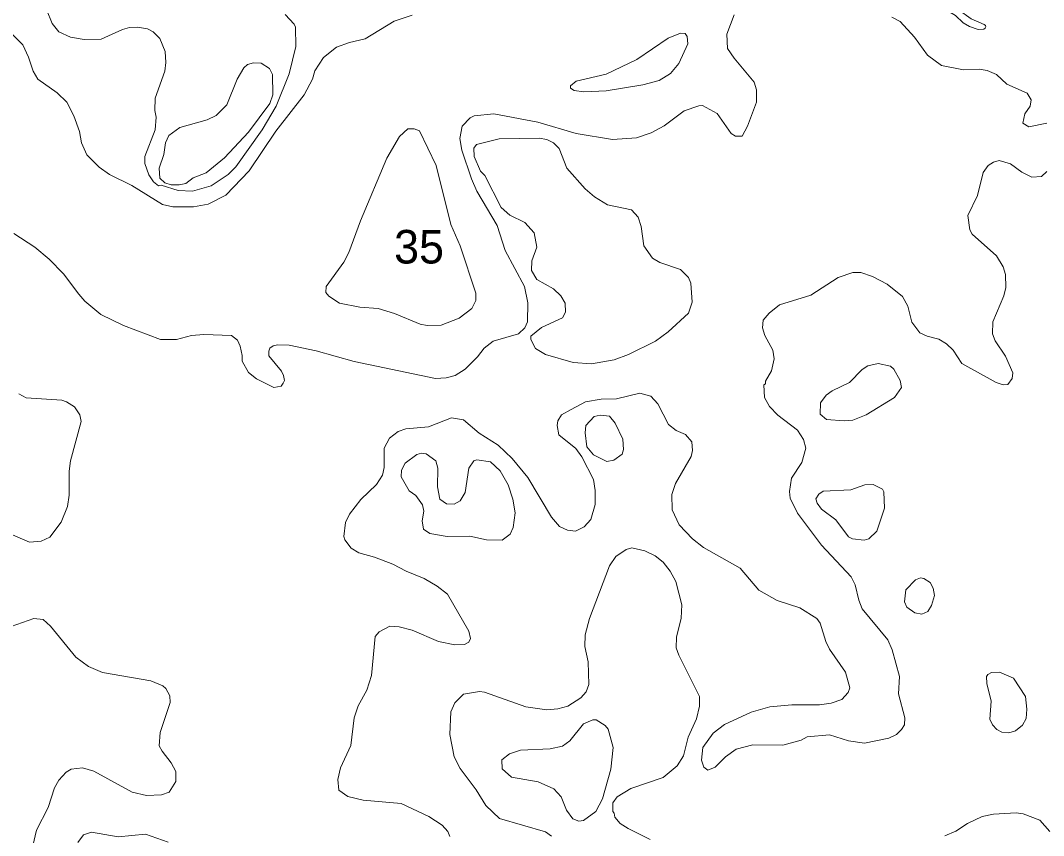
# Model space of a CAD drawing. Extents: x 673.6 to 698.9, y 7012 to 7040.1.
# Drawn here: x 683.554 to 685.993, y 7022.356 to 7024.299 of the extents above; entities that cross this region are included whole.
import ezdxf

# ---------------------------------------------------------------- set-up
doc = ezdxf.new("R2010")
doc.units = 0
doc.header["$LTSCALE"] = 0.032
doc.layers.add('2', color=7, linetype='Continuous', lineweight=13)
doc.layers.add('21', color=7, linetype='Continuous')

msp = doc.modelspace()

# ---------------------------------------------------------------- linework, layer by layer
at = {"layer": '2'}
for points in [[(683.4069, 7024.4178), (683.4577, 7024.3597), (683.4897, 7024.3113), (683.5591, 7024.2409), (683.5731, 7024.2116), (683.5839, 7024.1784)], [(683.6159, 7024.325), (683.6289, 7024.2922), (683.6455, 7024.2721), (683.6731, 7024.2592), (683.7052, 7024.254), (683.7463, 7024.2547), (683.7967, 7024.2777), (683.814, 7024.2827), (683.8327, 7024.2835), (683.8563, 7024.2794), (683.8701, 7024.2718), (683.8858, 7024.256), (683.8984, 7024.2251), (683.9003, 7024.1993), (683.8978, 7024.1784), (683.8747, 7024.114), (683.874, 7024.0848), (683.8772, 7024.0686), (683.8748, 7024.0387), (683.8502, 7023.9746), (683.8502, 7023.958), (683.8596, 7023.9313), (683.8712, 7023.9142), (683.8827, 7023.905), (683.8892, 7023.9061), (683.9296, 7023.8936), (683.9639, 7023.8925), (684.0086, 7023.9051), (684.049, 7023.9321), (684.0674, 7023.9502), (684.1301, 7024.0381), (684.1634, 7024.095), (684.1945, 7024.1722), (684.2099, 7024.2372), (684.2092, 7024.2831), (684.2063, 7024.2906), (684.185, 7024.3132)], [(683.5839, 7024.1784), (683.5954, 7024.1596), (683.6414, 7024.1265), (683.6644, 7024.1044), (683.6811, 7024.0716), (683.6941, 7024.0342), (683.6991, 7024.0071), (683.7121, 7023.9786), (683.7411, 7023.9496), (683.7657, 7023.9322), (683.8189, 7023.9055), (683.8924, 7023.8601), (683.917, 7023.855), (683.9665, 7023.8546), (684.0013, 7023.8612), (684.0435, 7023.8828), (684.0988, 7023.9406), (684.1621, 7024.0351), (684.2304, 7024.1222), (684.2496, 7024.159), (684.2554, 7024.1787), (684.2759, 7024.2112), (684.3073, 7024.2352), (684.3384, 7024.247), (684.3757, 7024.2555), (684.4448, 7024.2974), (684.4875, 7024.3122)], [(685.2552, 7024.3124), (685.2375, 7024.2662), (685.2394, 7024.2326), (685.2555, 7024.209), (685.303, 7024.1521), (685.3087, 7024.134), (685.3087, 7024.1044), (685.2867, 7024.0472), (685.2741, 7024.0235), (685.258, 7024.0234), (685.2484, 7024.0294), (685.2143, 7024.0773), (685.1798, 7024.0962), (685.1709, 7024.096), (685.1364, 7024.0836), (685.0881, 7024.0483), (685.0575, 7024.0309), (685.0222, 7024.019)], [(686.0009, 7024.0545), (685.958, 7024.0453), (685.9433, 7024.0545), (685.9479, 7024.0762), (685.9613, 7024.0947), (685.9635, 7024.1103), (685.9537, 7024.1256), (685.9056, 7024.147), (685.8805, 7024.1702), (685.8585, 7024.18), (685.8395, 7024.1832), (685.8023, 7024.1817), (685.7492, 7024.1916), (685.7161, 7024.2164), (685.6849, 7024.2592), (685.6506, 7024.2967), (685.6311, 7024.3068)], [(684.6357, 7024.0715), (684.626, 7024.0674), (684.6064, 7024.0472), (684.6013, 7024.0178), (684.6059, 7023.99), (684.6287, 7023.9214), (684.6417, 7023.8921), (684.6899, 7023.8102), (684.7096, 7023.751), (684.7552, 7023.665), (684.7633, 7023.6261), (684.7624, 7023.5808), (684.7565, 7023.5662), (684.7413, 7023.5522), (684.6804, 7023.5349), (684.6588, 7023.5176), (684.6431, 7023.497), (684.6136, 7023.4674), (684.5903, 7023.4523), (684.5689, 7023.4469), (684.543, 7023.4454), (684.3492, 7023.4861), (684.2588, 7023.5113), (684.1943, 7023.5249), (684.167, 7023.5259), (684.156, 7023.5236), (684.1485, 7023.5182), (684.1456, 7023.5106), (684.146, 7023.4995), (684.1757, 7023.4631), (684.1808, 7023.4526), (684.183, 7023.441), (684.1802, 7023.4343), (684.1754, 7023.4274), (684.1578, 7023.4241), (684.1161, 7023.4447), (684.0977, 7023.4599), (684.0819, 7023.4869), (684.0826, 7023.5), (684.0776, 7023.5228), (684.0709, 7023.5366), (684.0571, 7023.5479), (683.9908, 7023.5505), (683.9612, 7023.5479), (683.9257, 7023.5383), (683.8876, 7023.5383), (683.7991, 7023.5717), (683.7454, 7023.5984), (683.7069, 7023.6299), (683.693, 7023.6468), (683.6564, 7023.695), (683.622, 7023.7303), (683.5882, 7023.759), (683.5379, 7023.7913)], [(685.0222, 7024.019), (684.9654, 7024.0157), (684.8787, 7024.0297), (684.7869, 7024.0567), (684.6824, 7024.0763), (684.6357, 7024.0715)], [(685.2347, 7022.5438), (685.2598, 7022.5616), (685.2997, 7022.5718), (685.3711, 7022.5711), (685.4146, 7022.5834), (685.4294, 7022.5909), (685.4828, 7022.5955), (685.5281, 7022.5816), (685.5656, 7022.576), (685.6238, 7022.5876), (685.6421, 7022.5969), (685.6543, 7022.6083), (685.6612, 7022.6199), (685.6621, 7022.6364), (685.6474, 7022.6936), (685.6496, 7022.7353), (685.632, 7022.7988), (685.6217, 7022.8225), (685.5606, 7022.896), (685.5523, 7022.9167), (685.5437, 7022.9539), (685.5343, 7022.9726), (685.4637, 7023.0479), (685.4059, 7023.1246), (685.3888, 7023.1599), (685.3869, 7023.1761), (685.3922, 7023.2077), (685.4167, 7023.2455), (685.4262, 7023.2794), (685.4209, 7023.2998), (685.4062, 7023.3223), (685.3591, 7023.358), (685.3391, 7023.3787), (685.3274, 7023.4), (685.3262, 7023.4305), (685.3298, 7023.4329), (685.3302, 7023.4392), (685.3444, 7023.4641), (685.3506, 7023.4923), (685.3471, 7023.513), (685.3281, 7023.5479), (685.3226, 7023.5665), (685.3247, 7023.5843), (685.3383, 7023.6014), (685.3635, 7023.6211), (685.438, 7023.6444), (685.5032, 7023.686), (685.5384, 7023.6985), (685.5574, 7023.6985), (685.5854, 7023.6888), (685.6202, 7023.6707), (685.6563, 7023.6409), (685.6693, 7023.6182), (685.6785, 7023.5802), (685.6982, 7023.5546), (685.7152, 7023.5466), (685.7428, 7023.5393), (685.7613, 7023.5285), (685.7774, 7023.5133), (685.7978, 7023.4815), (685.8798, 7023.4363), (685.8967, 7023.4306), (685.9077, 7023.4315), (685.9184, 7023.4454), (685.9193, 7023.459), (685.9025, 7023.4985), (685.8773, 7023.5357), (685.8709, 7023.5523), (685.8717, 7023.5806), (685.8979, 7023.6427), (685.9028, 7023.6624), (685.9018, 7023.6931), (685.8962, 7023.7118), (685.8809, 7023.7377), (685.8228, 7023.7899), (685.8167, 7023.8), (685.8126, 7023.8344), (685.8354, 7023.8822), (685.8486, 7023.9368), (685.861, 7023.9532), (685.8732, 7023.9613), (685.8871, 7023.9654), (685.9143, 7023.9572), (685.941, 7023.9374), (685.9647, 7023.9255), (685.9876, 7023.9273), (686.0006, 7023.9393)], [(684.359, 7022.665), (684.3792, 7022.7022), (684.3908, 7022.7374), (684.3994, 7022.8304), (684.4088, 7022.8417), (684.4341, 7022.8547), (684.4567, 7022.8537), (684.4873, 7022.8451), (684.5506, 7022.8182), (684.5892, 7022.8105), (684.6121, 7022.8115), (684.6226, 7022.817), (684.6265, 7022.8252), (684.6225, 7022.8432), (684.5715, 7022.9311), (684.5475, 7022.9502), (684.5162, 7022.9689), (684.4735, 7022.9859), (684.4415, 7023.0026), (684.3977, 7023.0196), (684.3602, 7023.03), (684.3424, 7023.0411), (684.3268, 7023.0609), (684.3243, 7023.0691), (684.3285, 7023.1018), (684.3383, 7023.1217), (684.3648, 7023.1572), (684.4026, 7023.1927), (684.4169, 7023.2151), (684.4204, 7023.2333), (684.4209, 7023.2793), (684.4331, 7023.3034), (684.4538, 7023.3194), (684.4725, 7023.3257), (684.5261, 7023.3301), (684.5812, 7023.3517), (684.6097, 7023.3473), (684.6475, 7023.3148), (684.6926, 7023.2869), (684.7259, 7023.255), (684.7629, 7023.2098), (684.8199, 7023.1152), (684.839, 7023.0925), (684.8577, 7023.0839), (684.877, 7023.0814), (684.8972, 7023.0916), (684.9134, 7023.1091), (684.9242, 7023.1453), (684.9242, 7023.1788), (684.9197, 7023.2045), (684.8917, 7023.2587), (684.878, 7023.2784), (684.8373, 7023.3114), (684.8333, 7023.3333), (684.8349, 7023.3445), (684.8437, 7023.3587), (684.8668, 7023.3718), (684.901, 7023.3897), (684.9378, 7023.396), (684.975, 7023.397), (685.0302, 7023.4108), (685.0562, 7023.4036), (685.0731, 7023.385), (685.0989, 7023.3355), (685.1169, 7023.3214), (685.139, 7023.3123), (685.1542, 7023.2943), (685.1559, 7023.2739), (685.1525, 7023.2593), (685.1157, 7023.1955), (685.1065, 7023.1689), (685.1073, 7023.1321), (685.1242, 7023.0968), (685.1562, 7023.0629), (685.182, 7023.0425), (685.2696, 7022.9932), (685.3141, 7022.9412), (685.3579, 7022.9159), (685.4121, 7022.8985), (685.4524, 7022.8733), (685.4606, 7022.8619), (685.4735, 7022.8186), (685.4825, 7022.8005), (685.5208, 7022.7449), (685.5306, 7022.7078), (685.5269, 7022.6971), (685.5122, 7022.6804), (685.4865, 7022.6716), (685.4586, 7022.6672), (685.3927, 7022.6671), (685.3402, 7022.6625), (685.2955, 7022.6502), (685.2318, 7022.6209), (685.205, 7022.5996), (685.1808, 7022.5654)], [(683.5499, 7023.4086), (683.5672, 7023.3991), (683.652, 7023.3935), (683.6631, 7023.3902), (683.6824, 7023.3778), (683.6955, 7023.3587), (683.698, 7023.3431), (683.6726, 7023.2495), (683.6694, 7023.2246), (683.6701, 7023.1677), (683.6661, 7023.1401), (683.6509, 7023.1029), (683.6233, 7023.0674), (683.6033, 7023.0578), (683.5754, 7023.0551), (683.5066, 7023.0846)], [(684.8198, 7022.3539), (684.8051, 7022.3646), (684.6961, 7022.3967), (684.6629, 7022.427), (684.6404, 7022.4645), (684.6016, 7022.5156), (684.588, 7022.5431), (684.5774, 7022.597), (684.5798, 7022.6504), (684.5895, 7022.6719), (684.6101, 7022.693), (684.6482, 7022.6991), (684.6603, 7022.6975), (684.7587, 7022.6627), (684.8085, 7022.6552), (684.835, 7022.6579), (684.8585, 7022.6645), (684.8898, 7022.684), (684.9027, 7022.6985), (684.9085, 7022.716), (684.9069, 7022.7696), (684.8991, 7022.8062), (684.8996, 7022.8344), (684.9104, 7022.8729), (684.958, 7022.9986), (684.9731, 7023.0211), (684.9974, 7023.0377), (685.0114, 7023.0417), (685.0421, 7023.0349), (685.067, 7023.0226), (685.0858, 7023.0076), (685.1027, 7022.9865), (685.1159, 7022.9616), (685.1304, 7022.906), (685.1287, 7022.8743), (685.118, 7022.8287), (685.1173, 7022.8031), (685.1232, 7022.7861), (685.1723, 7022.6871), (685.1723, 7022.6644), (685.1652, 7022.6342), (685.1456, 7022.5903), (685.1342, 7022.5456), (685.1197, 7022.5223), (685.0861, 7022.4938), (685.0085, 7022.4681), (684.9762, 7022.448), (684.9662, 7022.4338), (684.966, 7022.4127), (684.9693, 7022.4093), (684.9704, 7022.3992), (684.9837, 7022.3848), (685.0023, 7022.3723), (685.0551, 7022.3464)], [(683.5183, 7022.8497), (683.5852, 7022.8734), (683.6075, 7022.8709), (683.625, 7022.8553), (683.6859, 7022.7813), (683.7158, 7022.7585), (683.7489, 7022.7443), (683.8643, 7022.7249), (683.8934, 7022.7128), (683.8999, 7022.7067), (683.9095, 7022.6887)], [(683.9095, 7022.6887), (683.9108, 7022.6726), (683.8867, 7022.6017), (683.8847, 7022.5697), (683.8911, 7022.5566), (683.9132, 7022.5294)], [(684.3126, 7022.464), (684.3104, 7022.4895), (684.3165, 7022.5173), (684.3414, 7022.5707), (684.3496, 7022.6364), (684.359, 7022.665)], [(685.1808, 7022.5654), (685.1772, 7022.5357), (685.1831, 7022.5188), (685.1926, 7022.5119), (685.2101, 7022.519), (685.2347, 7022.5438)], [(683.9132, 7022.5294), (683.9241, 7022.5082), (683.924, 7022.4845), (683.9079, 7022.4588), (683.8903, 7022.4528), (683.8543, 7022.4511), (683.8196, 7022.4591), (683.7285, 7022.5093), (683.7013, 7022.5168), (683.6747, 7022.5143), (683.6629, 7022.5069), (683.6453, 7022.4881), (683.6348, 7022.4692), (683.6199, 7022.4228), (683.592, 7022.3688), (683.5831, 7022.3313)], [(684.5772, 7022.3531), (684.5727, 7022.3655), (684.5591, 7022.3804), (684.5272, 7022.4009), (684.4612, 7022.4322), (684.3706, 7022.4402), (684.3344, 7022.449), (684.3126, 7022.464)], [(686.008, 7022.3657), (685.984, 7022.3924), (685.9446, 7022.4072), (685.9275, 7022.4099), (685.8734, 7022.4066), (685.8467, 7022.4008), (685.8112, 7022.3845), (685.7838, 7022.366), (685.7573, 7022.3551)], [(683.6906, 7022.339), (683.7041, 7022.3573), (683.7233, 7022.3638), (683.7866, 7022.3525), (683.8515, 7022.359), (683.906, 7022.3402)]]:
    msp.add_lwpolyline(points, dxfattribs=at)
for points in [[(685.7106, 7024.3672), (685.7895, 7024.3256), (685.8204, 7024.3034), (685.8515, 7024.2895), (685.8547, 7024.2868), (685.8549, 7024.2838), (685.8536, 7024.2805), (685.8502, 7024.2784), (685.8371, 7024.2778), (685.8159, 7024.2844), (685.8009, 7024.2936), (685.7827, 7024.3113), (685.7226, 7024.347), (685.6652, 7024.3712), (685.6634, 7024.3742), (685.6627, 7024.3772), (685.6652, 7024.3805), (685.6703, 7024.3808), (685.6777, 7024.3788)], [(685.0977, 7024.2571), (685.1272, 7024.2686), (685.1381, 7024.2679), (685.1435, 7024.2609), (685.1451, 7024.2433), (685.123, 7024.1965), (685.1038, 7024.1727), (685.0766, 7024.1561), (685.0371, 7024.1456), (684.9501, 7024.1314), (684.8967, 7024.1291), (684.8741, 7024.1324), (684.8651, 7024.1374), (684.8648, 7024.143), (684.8782, 7024.1544), (684.9503, 7024.1712), (685.023, 7024.2061)], [(683.8861, 7023.9229), (683.8982, 7023.9119), (683.9126, 7023.9074), (683.9317, 7023.9069), (683.9476, 7023.9104), (683.9652, 7023.9236), (683.9964, 7023.936), (684.0402, 7023.9716), (684.0971, 7024.0326), (684.1484, 7024.1011), (684.1557, 7024.1222), (684.1542, 7024.1707), (684.1471, 7024.1846), (684.1272, 7024.1973), (684.1093, 7024.1981), (684.0951, 7024.1938), (684.0864, 7024.186), (684.0707, 7024.1593), (684.046, 7024.0984), (684.0205, 7024.0723), (683.9987, 7024.0619), (683.9334, 7024.0441), (683.9071, 7024.0248), (683.8995, 7024.0075), (683.8953, 7023.9796), (683.8847, 7023.947)], [(684.4269, 7023.971), (684.4571, 7024.0228), (684.477, 7024.0404), (684.4926, 7024.0411), (684.5054, 7024.0357), (684.5444, 7023.9535), (684.5798, 7023.8127), (684.6023, 7023.7618), (684.6394, 7023.6491), (684.6392, 7023.6318), (684.6297, 7023.6128), (684.5995, 7023.5892), (684.5568, 7023.5728), (684.5229, 7023.572), (684.5066, 7023.575), (684.4454, 7023.6005), (684.4067, 7023.6123), (684.3626, 7023.6155), (684.3142, 7023.6252), (684.2892, 7023.6415), (684.2816, 7023.6503), (684.2824, 7023.6646), (684.3247, 7023.7225), (684.3366, 7023.7458), (684.3643, 7023.8217)], [(684.8458, 7023.5898), (684.8534, 7023.6039), (684.8526, 7023.6248), (684.8418, 7023.6429), (684.8248, 7023.6592), (684.7849, 7023.6819), (684.7719, 7023.7027), (684.773, 7023.7261), (684.7844, 7023.7587), (684.7785, 7023.7927), (684.7561, 7023.8172), (684.7202, 7023.835), (684.6999, 7023.8535), (684.661, 7023.9294), (684.6505, 7023.94), (684.6351, 7023.9751), (684.6345, 7023.9948), (684.6411, 7024.0034), (684.6949, 7024.0173), (684.7906, 7024.0188), (684.8085, 7024.015), (684.8244, 7024.0076), (684.8377, 7023.9937), (684.8562, 7023.9473), (684.9001, 7023.8976), (684.9219, 7023.8783), (684.9529, 7023.8594), (685.0106, 7023.848), (685.026, 7023.8299), (685.0331, 7023.8081), (685.0402, 7023.7622), (685.0605, 7023.7322), (685.0782, 7023.7221), (685.1271, 7023.705), (685.1464, 7023.6862), (685.152, 7023.6731), (685.155, 7023.6279), (685.1466, 7023.6012), (685.0978, 7023.5566), (685.0677, 7023.5348), (685.0034, 7023.5026), (684.969, 7023.4904), (684.9147, 7023.4807), (684.871, 7023.4836), (684.8055, 7023.5031), (684.7814, 7023.5168), (684.7707, 7023.5385), (684.7707, 7023.5465), (684.7958, 7023.5674)], [(685.6538, 7023.4243), (685.6512, 7023.4411), (685.6357, 7023.4675), (685.6279, 7023.4747), (685.5988, 7023.4816), (685.5742, 7023.4757), (685.5607, 7023.4672), (685.5303, 7023.436), (685.4888, 7023.4158), (685.4745, 7023.4056), (685.4608, 7023.3877), (685.4606, 7023.3606), (685.4755, 7023.3476), (685.5172, 7023.3442), (685.5382, 7023.346), (685.5701, 7023.3586), (685.6373, 7023.4003)], [(684.9014, 7023.3338), (684.9214, 7023.3551), (684.9354, 7023.3583), (684.9576, 7023.3553), (684.9715, 7023.3391), (684.9899, 7023.3007), (684.9915, 7023.2761), (684.9881, 7023.2647), (684.9685, 7023.2507), (684.9517, 7023.2473), (684.9198, 7023.2633), (684.9037, 7023.2822), (684.8996, 7023.3161)], [(684.6227, 7023.2317), (684.6343, 7023.249), (684.6417, 7023.2513), (684.674, 7023.2466), (684.6971, 7023.2254), (684.7163, 7023.1919), (684.7277, 7023.1577), (684.7327, 7023.1249), (684.7284, 7023.09), (684.7211, 7023.0741), (684.702, 7023.0599), (684.6648, 7023.0608), (684.6252, 7023.0699), (684.5709, 7023.0691), (684.5293, 7023.0763), (684.5142, 7023.0863), (684.5117, 7023.1059), (684.5156, 7023.1289), (684.5121, 7023.1446), (684.4965, 7023.1662), (684.4804, 7023.1775), (684.4616, 7023.2107), (684.4624, 7023.2273), (684.4711, 7023.2438), (684.499, 7023.2646), (684.5096, 7023.2676), (684.5209, 7023.2661), (684.5436, 7023.2494), (684.5487, 7023.2314), (684.5479, 7023.187), (684.5534, 7023.1576), (684.5693, 7023.1463), (684.5877, 7023.1455), (684.6021, 7023.1538), (684.6136, 7023.1736)], [(685.6121, 7023.1755), (685.6092, 7023.1815), (685.5867, 7023.1926), (685.5667, 7023.1923), (685.5335, 7023.18), (685.4677, 7023.1766), (685.4573, 7023.1698), (685.4501, 7023.1589), (685.4531, 7023.1484), (685.4636, 7023.1338), (685.4977, 7023.1084), (685.5276, 7023.0679), (685.5375, 7023.063), (685.5655, 7023.06), (685.5765, 7023.0634), (685.5956, 7023.0818), (685.6136, 7023.1364)], [(685.7326, 7022.928), (685.7295, 7022.9458), (685.7227, 7022.9589), (685.7076, 7022.9685), (685.6993, 7022.9702), (685.6872, 7022.9657), (685.6646, 7022.9413), (685.6614, 7022.9132), (685.667, 7022.8999), (685.6858, 7022.8864), (685.7026, 7022.8835), (685.7167, 7022.8896), (685.7258, 7022.904)], [(685.921, 7022.731), (685.8881, 7022.7452), (685.8689, 7022.7444), (685.8597, 7022.7395), (685.8569, 7022.7346), (685.8577, 7022.7186), (685.8683, 7022.6759), (685.8651, 7022.6335), (685.8711, 7022.6194), (685.8814, 7022.6083), (685.893, 7022.6023), (685.9097, 7022.6007), (685.9256, 7022.6054), (685.9423, 7022.6186), (685.951, 7022.6345), (685.9531, 7022.6569), (685.9497, 7022.6874)], [(684.8553, 7022.4166), (684.8427, 7022.448), (684.8251, 7022.4671), (684.7883, 7022.484), (684.7241, 7022.4952), (684.7024, 7022.5145), (684.7015, 7022.5361), (684.7198, 7022.5506), (684.7458, 7022.5595), (684.8162, 7022.5628), (684.8458, 7022.5692), (684.8631, 7022.5815), (684.8957, 7022.6219), (684.9184, 7022.6318), (684.926, 7022.6317), (684.9474, 7022.6183), (684.9551, 7022.609), (684.9668, 7022.5658), (684.9612, 7022.5139), (684.9417, 7022.4435), (684.9253, 7022.4127), (684.8957, 7022.3917), (684.8847, 7022.3903), (684.8706, 7022.3958)]]:
    msp.add_lwpolyline(points, close=True, dxfattribs=at)

# ---------------------------------------------------------------- texts
at = {"layer": '21'}
msp.add_text('35', height=0.08, dxfattribs=at).set_placement((684.4444, 7023.7197))

doc.saveas('drawing.dxf')
